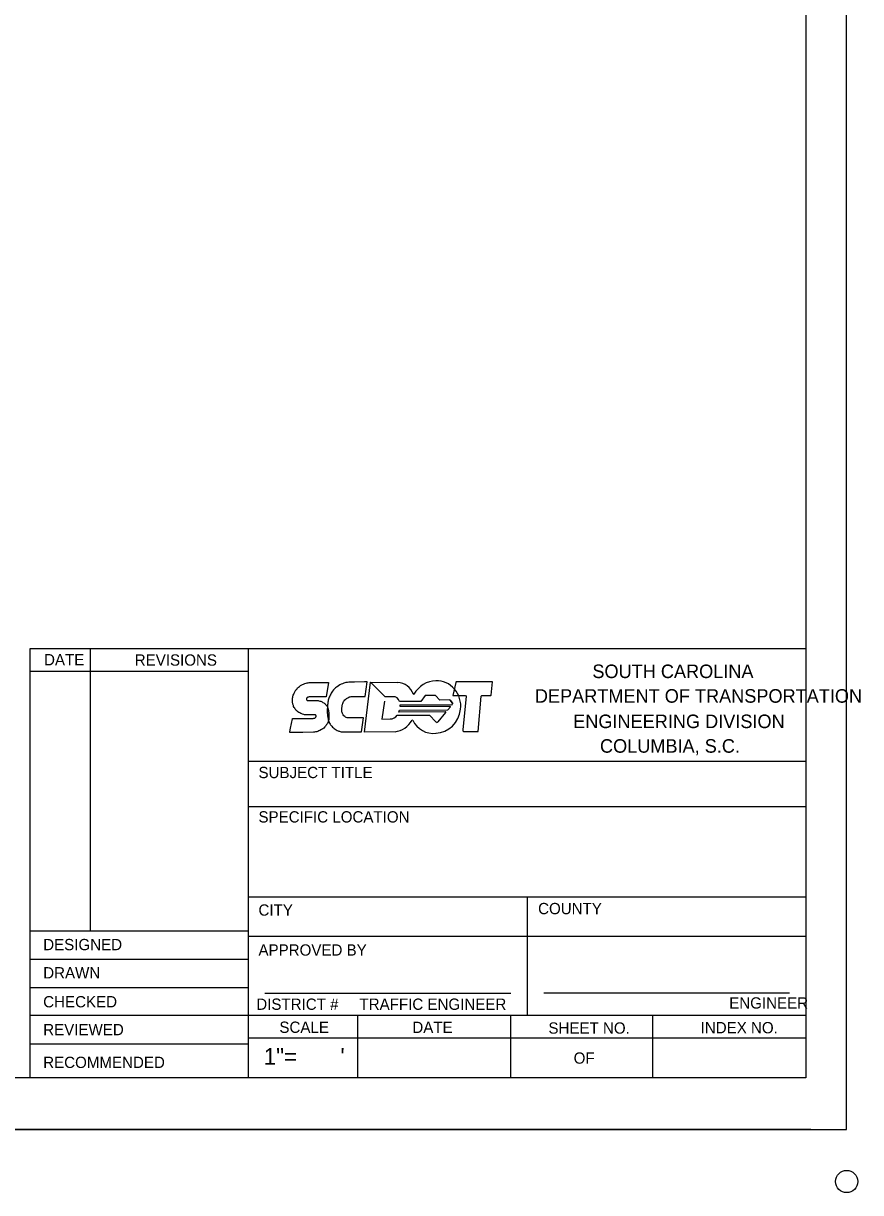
# Model space of a CAD drawing. Extents: x 0 to 3.01, y -0.05 to 1.83.
# Drawn here: x 2.337 to 3.011, y -0.051 to 0.891 of the extents above; entities that cross this region are included whole.
import ezdxf

# ---------------------------------------------------------------- set-up
doc = ezdxf.new("R2010")
doc.units = 0
doc.layers.add('RD_SHT_IplotShp', color=7, linetype='Continuous')
doc.layers.add('TR_TS_Border', color=7, linetype='Continuous')

msp = doc.modelspace()

# ---------------------------------------------------------------- linework, layer by layer
at = {"layer": 'RD_SHT_IplotShp'}
msp.add_lwpolyline([(0, 0), (3, 0), (3, 1.83333), (0, 1.83333)], close=True, dxfattribs=at)
at = {"layer": 'TR_TS_Border'}
for p, q in [((3, 0), (3, 1.83333)), ((2.96724, 1.78203), (2.96724, 0.04167)), ((2.3421, 0.38741), (2.96724, 0.38741)), ((2.3421, 0.04167), (2.3421, 0.38741)), ((2.39053, 0.38741), (2.39053, 0.15995)), ((2.5182, 0.04167), (2.5182, 0.38741)), ((2.3421, 0.36921), (2.5182, 0.36921)), ((2.61144, 0.32008), (2.61646, 0.36029)), ((2.62817, 0.34865), (2.61646, 0.36029)), ((2.61646, 0.36029), (2.63829, 0.3602)), ((2.61646, 0.36029), (2.62817, 0.34865)), ((2.68505, 0.36011), (2.68285, 0.34974)), ((2.68522, 0.36047), (2.68505, 0.36011)), ((2.68584, 0.36057), (2.68531, 0.36057)), ((2.71384, 0.36066), (2.68584, 0.36057)), ((2.71349, 0.34983), (2.71481, 0.36066)), ((2.71454, 0.36066), (2.71384, 0.36066)), ((2.71481, 0.36066), (2.71454, 0.36066)), ((2.63468, 0.34865), (2.62817, 0.34865)), ((2.66057, 0.34956), (2.65705, 0.34492)), ((2.66867, 0.34965), (2.66057, 0.34956)), ((2.67228, 0.34592), (2.66867, 0.34965)), ((2.68285, 0.34974), (2.69306, 0.34965)), ((2.6935, 0.3491), (2.69086, 0.32199)), ((2.7031, 0.32071), (2.70565, 0.3491)), ((2.70609, 0.34956), (2.71322, 0.34956)), ((2.62764, 0.3451), (2.62553, 0.33063)), ((2.65705, 0.34492), (2.63979, 0.34483)), ((2.64023, 0.34219), (2.68188, 0.34246)), ((2.68073, 0.34082), (2.64023, 0.34064)), ((2.6802, 0.34601), (2.67228, 0.34592)), ((2.6788, 0.33809), (2.68091, 0.34055)), ((2.68056, 0.34592), (2.68258, 0.34346)), ((2.68056, 0.34592), (2.68258, 0.34346)), ((2.68258, 0.34346), (2.68056, 0.34592)), ((2.68188, 0.34246), (2.68196, 0.34201)), ((2.68196, 0.34201), (2.68214, 0.34191)), ((2.68214, 0.34191), (2.68258, 0.34291)), ((2.62553, 0.33063), (2.63231, 0.33081)), ((2.63794, 0.33373), (2.66391, 0.33391)), ((2.67686, 0.33636), (2.63935, 0.33618)), ((2.63979, 0.33791), (2.6788, 0.33809)), ((2.66391, 0.33391), (2.66902, 0.32836)), ((2.67078, 0.32836), (2.67703, 0.336)), ((2.69086, 0.32199), (2.69086, 0.32117)), ((2.69121, 0.32071), (2.7031, 0.32071)), ((2.63618, 0.32026), (2.61144, 0.32008)), ((2.96724, 0.29642), (2.5182, 0.29642)), ((2.96724, 0.26003), (2.5182, 0.26003)), ((2.96724, 0.18724), (2.5182, 0.18724)), ((2.74272, 0.18724), (2.74272, 0.09171)), ((2.3421, 0.15995), (2.5182, 0.15995)), ((2.96724, 0.1554), (2.5182, 0.1554)), ((2.3421, 0.1372), (2.5182, 0.1372)), ((2.3421, 0.11446), (2.5182, 0.11446)), ((2.5314, 0.10991), (2.72951, 0.10991)), ((2.95403, 0.10991), (2.75592, 0.10991)), ((2.96724, 0.09171), (2.3421, 0.09171)), ((2.60624, 0.04167), (2.60624, 0.09171)), ((2.72951, 0.04167), (2.72951, 0.09171)), ((2.84397, 0.04167), (2.84397, 0.09171)), ((2.3421, 0.06896), (2.5182, 0.06896)), ((2.96724, 0.07351), (2.5182, 0.07351)), ((2.96724, 0.04167), (0.16861, 0.04167)), ((2.97124, 0), (0.031, 0))]:
    msp.add_line(p, q, dxfattribs=at)
for points in [[(2.56099, 0.33482), (2.56028, 0.33518), (2.5594, 0.33555), (2.55861, 0.33591), (2.55791, 0.33636), (2.5572, 0.337), (2.55658, 0.33764), (2.55614, 0.338), (2.55562, 0.33873), (2.55535, 0.33937), (2.555, 0.34009), (2.55447, 0.34082), (2.5543, 0.34155), (2.55403, 0.3421), (2.55394, 0.34273), (2.55377, 0.34328), (2.55368, 0.34373), (2.55368, 0.34437), (2.55368, 0.34574), (2.55368, 0.34637), (2.55368, 0.34746), (2.55377, 0.34837), (2.55394, 0.3491), (2.55421, 0.35001), (2.55456, 0.35083), (2.55491, 0.35156), (2.55535, 0.35247), (2.55562, 0.3531), (2.55623, 0.35411), (2.55694, 0.35483), (2.55764, 0.35574), (2.55843, 0.35647), (2.55914, 0.35693), (2.55993, 0.35756), (2.56099, 0.3582), (2.56152, 0.35847), (2.5624, 0.35884), (2.56301, 0.35911), (2.56363, 0.35938), (2.56451, 0.35966), (2.56539, 0.35984), (2.56618, 0.35993), (2.56697, 0.36002), (2.56759, 0.36002), (2.56829, 0.36002), (2.57736, 0.36011), (2.58265, 0.36011)], [(2.58265, 0.36011), (2.5808, 0.34846), (2.56689, 0.34846), (2.56645, 0.34837), (2.56592, 0.34828), (2.56565, 0.3481), (2.56539, 0.34792), (2.56512, 0.34774), (2.56504, 0.34756), (2.56495, 0.34737), (2.56486, 0.3471), (2.56477, 0.34683), (2.56477, 0.34665), (2.56477, 0.34628), (2.56486, 0.34628), (2.56504, 0.34592), (2.56512, 0.34583), (2.5653, 0.34574), (2.56565, 0.34564), (2.56583, 0.34564), (2.56627, 0.34555), (2.56733, 0.34555), (2.56829, 0.34564), (2.569, 0.34564), (2.56988, 0.34574), (2.57252, 0.34574)], [(2.58229, 0.34592), (2.58221, 0.3451), (2.58203, 0.34419), (2.58194, 0.34301), (2.58185, 0.34219), (2.58185, 0.34128), (2.58185, 0.341), (2.58177, 0.34064), (2.58177, 0.34037), (2.58168, 0.34), (2.58168, 0.33955), (2.58168, 0.33918), (2.58159, 0.33882), (2.58159, 0.33818), (2.58159, 0.33773), (2.58159, 0.33727), (2.58159, 0.33682), (2.58159, 0.33655), (2.58159, 0.33609), (2.58159, 0.33555), (2.58168, 0.33473), (2.58177, 0.33391), (2.58185, 0.33318), (2.58194, 0.33254), (2.58203, 0.33172), (2.58221, 0.33118), (2.58221, 0.33063), (2.58229, 0.33009), (2.58256, 0.32936), (2.58273, 0.32872), (2.58282, 0.32827), (2.58335, 0.32745), (2.58388, 0.32663), (2.58423, 0.32599), (2.58467, 0.32536), (2.5852, 0.32481), (2.5859, 0.32408), (2.58652, 0.32354), (2.58714, 0.32299), (2.58784, 0.32244), (2.58881, 0.32199), (2.5896, 0.32144), (2.59022, 0.32117), (2.59092, 0.3209), (2.59154, 0.32081), (2.59198, 0.32062), (2.59286, 0.32044), (2.5933, 0.32044), (2.594, 0.32026), (2.59453, 0.32026), (2.60906, 0.32026), (2.60915, 0.32044), (2.60924, 0.32044), (2.61065, 0.33163), (2.61021, 0.33163), (2.59938, 0.33154), (2.59841, 0.33163), (2.59761, 0.33172), (2.59691, 0.33191), (2.59621, 0.33227), (2.59559, 0.33272), (2.59489, 0.33336), (2.59436, 0.334), (2.594, 0.33454), (2.59374, 0.33518), (2.59348, 0.33582), (2.5933, 0.33636), (2.59321, 0.33727), (2.5933, 0.33837), (2.59339, 0.33937), (2.59348, 0.34064), (2.59356, 0.34137), (2.59374, 0.34255), (2.594, 0.34319), (2.59436, 0.34392), (2.59471, 0.34473), (2.59515, 0.34546), (2.59585, 0.34601), (2.59647, 0.34674), (2.59709, 0.34728), (2.59814, 0.34783), (2.59894, 0.34828), (2.59955, 0.34846), (2.59999, 0.34856), (2.60078, 0.34874), (2.60166, 0.34874), (2.61205, 0.34874), (2.61223, 0.34883), (2.61382, 0.36066)], [(2.61382, 0.36066), (2.61161, 0.36066), (2.60343, 0.36029), (2.6007, 0.36029), (2.59902, 0.36029), (2.59788, 0.3602), (2.59647, 0.36002), (2.59559, 0.35984), (2.5948, 0.35956), (2.59383, 0.35911), (2.59286, 0.35875), (2.59172, 0.3582), (2.59057, 0.35747), (2.58943, 0.35665), (2.58899, 0.35629), (2.58828, 0.35574), (2.5874, 0.35502), (2.5867, 0.3542), (2.5859, 0.3532), (2.58538, 0.35229), (2.58476, 0.35147), (2.58441, 0.35083), (2.58397, 0.35001), (2.58361, 0.34919), (2.58309, 0.34828), (2.58282, 0.34746), (2.58256, 0.34665), (2.58229, 0.34592)], [(2.58159, 0.34082), (2.58177, 0.34037), (2.58185, 0.34), (2.58203, 0.33964), (2.58203, 0.33937), (2.58221, 0.339), (2.58229, 0.33846), (2.58238, 0.33818), (2.58238, 0.338), (2.58247, 0.33773), (2.58256, 0.33746), (2.58256, 0.33727), (2.58256, 0.33709), (2.58265, 0.33691), (2.58265, 0.33655), (2.58273, 0.33618), (2.58273, 0.33591), (2.58282, 0.33573), (2.58282, 0.33536), (2.58282, 0.33518), (2.58291, 0.33482), (2.58291, 0.33454), (2.58291, 0.33409), (2.58291, 0.33382), (2.58291, 0.33382), (2.58291, 0.33345), (2.58291, 0.33309), (2.58291, 0.33272), (2.58291, 0.33254), (2.58291, 0.33245), (2.58291, 0.33218), (2.58291, 0.33181), (2.58291, 0.33154), (2.58282, 0.33127), (2.58282, 0.3309), (2.58282, 0.33063), (2.58273, 0.33045), (2.58273, 0.33009), (2.58265, 0.3299), (2.58256, 0.32963), (2.58247, 0.32936), (2.58247, 0.32909), (2.58238, 0.3289), (2.58229, 0.32863), (2.58221, 0.32818), (2.58203, 0.32781), (2.58177, 0.32708), (2.5815, 0.32672), (2.58106, 0.32626), (2.58089, 0.32599), (2.58053, 0.32554), (2.58009, 0.3249), (2.57948, 0.32426), (2.57868, 0.32344), (2.57789, 0.32281), (2.57684, 0.32217), (2.57569, 0.32144), (2.57481, 0.32108), (2.57393, 0.32071), (2.57314, 0.32044), (2.57217, 0.32026), (2.5712, 0.32008), (2.57058, 0.32008), (2.56187, 0.3199), (2.55148, 0.3199), (2.5513, 0.32008), (2.5513, 0.32008), (2.5513, 0.32026), (2.5513, 0.32044), (2.55192, 0.32326), (2.5535, 0.3309), (2.5535, 0.331), (2.55368, 0.33118), (2.55368, 0.33118), (2.55412, 0.331), (2.56372, 0.33118), (2.57032, 0.33118), (2.57076, 0.33127), (2.57111, 0.33127), (2.57146, 0.33145), (2.5719, 0.33163), (2.57208, 0.33191), (2.57226, 0.33209), (2.57243, 0.33254), (2.57252, 0.33282), (2.57252, 0.33318), (2.57252, 0.33336), (2.57243, 0.33345), (2.57234, 0.33363), (2.57226, 0.33382), (2.57208, 0.334), (2.57182, 0.33409), (2.57164, 0.33418), (2.57146, 0.33418), (2.56424, 0.33409), (2.56389, 0.33409), (2.56363, 0.33418), (2.5631, 0.33418), (2.56266, 0.33436), (2.56169, 0.33454), (2.56099, 0.33482)], [(2.57252, 0.34574), (2.57331, 0.34564), (2.57411, 0.34555), (2.57481, 0.34537), (2.57569, 0.34519), (2.57631, 0.34501), (2.57692, 0.34473), (2.57736, 0.34455), (2.57807, 0.3441), (2.57886, 0.34364), (2.57939, 0.34319), (2.57992, 0.34291), (2.58027, 0.34246), (2.5808, 0.34182), (2.58106, 0.34146), (2.5815, 0.341), (2.58159, 0.34082)]]:
    msp.add_lwpolyline(points, dxfattribs=at)
msp.add_circle((3, -0.04199), 0.00894, dxfattribs=at)
for centre, major_axis, start_param, end_param in [((2.63752, 0.34494), (0, 0.01526), 5.101309, 6.228759), ((2.6696, 0.33907), (0, 0.02245), 0.022191, 1.026566), ((2.66966, 0.34103), (0, 0.02049), 4.590524, 6.310821), ((2.68529, 0.3604), (0, 0.000124), 0, 1.322539), ((2.63503, 0.34346), (0, 0.0052), 4.972804, 6.356492), ((2.65115, 0.35082), (0, 0.000247), 1.959716, 4.168159), ((2.69307, 0.34913), (0, -0.000494), 1.467405, 3.132152), ((2.7061, 0.34904), (0, 0.000494), 0, 1.477178), ((2.71317, 0.34991), (0, -0.000371), 0, 1.445107), ((2.62807, 0.34128), (0, 0.01283), 4.666228, 4.78426), ((2.68022, 0.34555), (0, 0.000494), 5.415198, 6.296193), ((2.68075, 0.34068), (0, 0.000185), 3.986308, 6.285649), ((2.68219, 0.34312), (0, -0.000494), 1.075193, 2.27985), ((2.63237, 0.3381), (0, -0.00733), 6.271457, 7.213216), ((2.62798, 0.34132), (0, -0.01293), 1.163643, 1.303168), ((2.65016, 0.32954), (0, -0.000247), 2.058368, 4.135244), ((2.66822, 0.34118), (0, -0.02202), 0.045208, 1.450715), ((2.67688, 0.33616), (0, 0.000247), 3.995698, 6.287734), ((2.63315, 0.3412), (0, -0.02112), 0.151273, 0.993651), ((2.6671, 0.33899), (0, -0.01993), 5.19996, 6.392752), ((2.66988, 0.32921), (0, -0.00124), 5.487728, 7.137097), ((2.69122, 0.32112), (0, -0.000371), 4.712389, 6.283185)]:
    msp.add_ellipse(centre, major_axis=major_axis, ratio=0.950042, start_param=start_param, end_param=end_param, dxfattribs=at)

# ---------------------------------------------------------------- texts
for s, height, p in [('DATE', 0.009098, (2.35341, 0.37394)), ('REVISIONS', 0.009098, (2.42647, 0.37367)), ('SOUTH CAROLINA', 0.010918, (2.79516, 0.36366)), ('DEPARTMENT OF TRANSPORTATION', 0.010918, (2.74881, 0.34382)), ('ENGINEERING DIVISION', 0.010918, (2.77969, 0.32335)), ('COLUMBIA, S.C.', 0.010918, (2.80128, 0.30352)), ('SUBJECT TITLE', 0.0090979, (2.52616, 0.28305)), ('SPECIFIC LOCATION', 0.0090979, (2.52616, 0.24729)), ('CITY', 0.009098, (2.52616, 0.17223)), ('COUNTY', 0.009098, (2.75143, 0.17341)), ('DESIGNED', 0.009098, (2.35273, 0.14439)), ('APPROVED BY', 0.0090979, (2.52616, 0.14002)), ('APPROVED BY', 0.0090979, (2.52616, 0.14002)), ('DRAWN', 0.009098, (2.35273, 0.12164)), ('CHECKED', 0.009098, (2.35273, 0.09835)), ('DISTRICT #     TRAFFIC ENGINEER', 0.0090985, (2.52438, 0.09635)), ('ENGINEER', 0.009098, (2.90538, 0.09735)), ('REVIEWED', 0.009098, (2.35273, 0.07588)), ('SCALE', 0.009098, (2.54302, 0.07779)), ('DATE', 0.009098, (2.65013, 0.0777)), ('SHEET NO.', 0.009098, (2.75975, 0.07715)), ('INDEX NO.', 0.009098, (2.88237, 0.07743)), ('RECOMMENDED', 0.0090985, (2.35273, 0.04949)), ('1"=       \'', 0.013434, (2.53038, 0.05206)), ('OF', 0.009098, (2.78006, 0.05295))]:
    msp.add_text(s, height=height, dxfattribs=at).set_placement(p)

doc.saveas('drawing.dxf')
